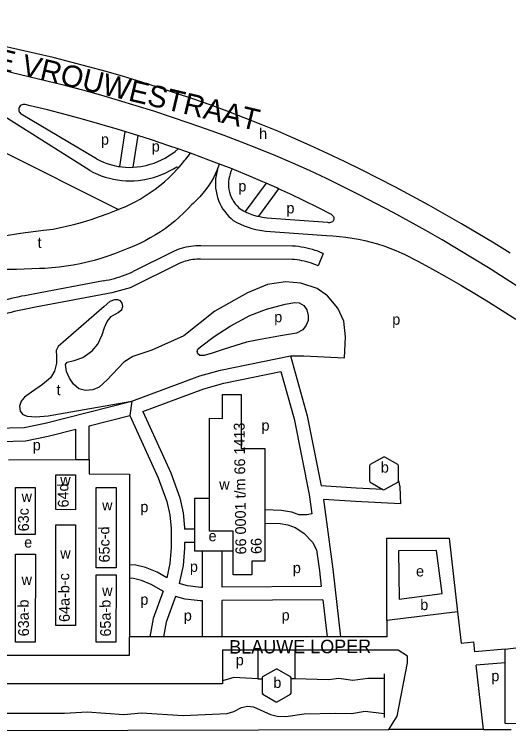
# Model space of a CAD drawing. Extents: x 161494 to 163033, y 383688 to 384862.
# Drawn here: x 162333.3 to 162517.1, y 384562.2 to 384828.7 of the extents above; entities that cross this region are included whole.
import ezdxf

# ---------------------------------------------------------------- set-up
doc = ezdxf.new("R2010")
doc.units = 0
for name, color, linetype in [('BLT_Basislijn', 7, 'Continuous'), ('BLT_Bebouwing', 7, 'Continuous'), ('BLT_Centroide', 7, 'Continuous'), ('BLT_Huisnummer', 7, 'Continuous'), ('BLT_Huisnummer_reeks', 7, 'Continuous'), ('BLT_Straatnaam', 7, 'Continuous'), ('BLT_Straatnaam_hoofdweg', 7, 'Continuous'), ('BLT_Vlakafsluiter', 7, 'Continuous')]:
    doc.layers.add(name, color=color, linetype=linetype)

msp = doc.modelspace()

# ---------------------------------------------------------------- linework, layer by layer
at = {"layer": 'BLT_Basislijn'}
for p, q in [((162361.38, 384770.68), (162323.86, 384794.28)), ((162363.88, 384775.02), (162335.93, 384791.64)), ((162309.6, 384787.43), (162372.08, 384756.07)), ((162374.39, 384785.15), (162372.4, 384772.1)), ((162379.22, 384783.64), (162377.42, 384771.83)), ((162397.07, 384774.81), (162398.79, 384777.02)), ((162403.4, 384775.36), (162398.79, 384777.02)), ((162393.74, 384772.05), (162394.6, 384771.89)), ((162408.89, 384771.07), (162409.65, 384773.01)), ((162426.93, 384765.9), (162419.17, 384755.33)), ((162431.6, 384763.82), (162424.1, 384753.58)), ((162374.26, 384756.97), (162372.08, 384756.07)), ((162427.26, 384753.06), (162449.71, 384751.4)), ((162426.8, 384748.08), (162449.34, 384746.42)), ((162436.81, 384742.53), (162402.64, 384742.61)), ((162392.77, 384740.63), (162377.48, 384733.02)), ((162436.62, 384737.54), (162402.57, 384737.61)), ((162361.15, 384675.62), (162376.28, 384679.48)), ((162361.15, 384663.08), (162361.15, 384675.62)), ((162356.15, 384663.06), (162356.15, 384674.35)), ((162331.14, 384662.94), (162356.15, 384663.06)), ((162356.15, 384663.06), (162361.15, 384663.08)), ((162361.15, 384663.08), (162361.14, 384657.72)), ((162400.33, 384637.25), (162396.65, 384637.25)), ((162400.33, 384637.25), (162400.33, 384632.25)), ((162400.33, 384632.25), (162396.65, 384632.25)), ((162403.3, 384629.13), (162410.56, 384629.14)), ((162403.3, 384615.53), (162403.3, 384629.13)), ((162410.56, 384629.14), (162414.74, 384629.14)), ((162410.56, 384615.59), (162410.56, 384629.14)), ((162376.15, 384623.95), (162376.16, 384618.93)), ((162376.16, 384618.93), (162376.17, 384597.18)), ((162447.44, 384615.89), (162410.56, 384615.59)), ((162403.3, 384597.18), (162403.3, 384610.53)), ((162448.02, 384610.89), (162410.56, 384610.59)), ((162410.56, 384597.18), (162410.56, 384610.59)), ((162448.02, 384610.89), (162449.6, 384597.18)), ((162383.67, 384597.18), (162376.17, 384597.18)), ((162403.3, 384597.18), (162388.76, 384597.18)), ((162449.6, 384597.18), (162410.56, 384597.18)), ((162504.5, 384591.5), (162504.14, 384595.33)), ((162515.79, 384592.53), (162504.5, 384591.5)), ((162515.8, 384587.51), (162515.79, 384592.53)), ((162437.61, 384592.18), (162423.88, 384592.18)), ((162423.88, 384592.18), (162423.88, 384581.56)), ((162437.61, 384592.18), (162437.61, 384581.56)), ((162515.8, 384587.51), (162505.05, 384586.53)), ((162507.72, 384562.68), (162505.05, 384586.53)), ((162470.79, 384583.35), (162470.79, 384581.63)), ((162423.88, 384581.56), (162425.45, 384581.56)), ((162437.61, 384581.56), (162436.23, 384581.56)), ((162470.79, 384581.63), (162470.79, 384568.61)), ((162470.79, 384568.61), (162470.79, 384567.08)), ((162289.61, 384562.22), (162472.53, 384562.61)), ((162507.72, 384562.68), (162472.53, 384562.61)), ((162507.72, 384562.68), (162518.08, 384562.69))]:
    msp.add_line(p, q, dxfattribs=at)
for points in [[(162431.34, 384785.21), (162425.07, 384787.77), (162418.78, 384790.26), (162412.45, 384792.67), (162406.1, 384795.01), (162399.72, 384797.27), (162393.31, 384799.45), (162386.88, 384801.56), (162380.43, 384803.6), (162373.95, 384805.55), (162367.45, 384807.44), (162360.92, 384809.24), (162354.38, 384810.97), (162347.81, 384812.62), (162341.23, 384814.19), (162334.63, 384815.68), (162328.01, 384817.1)], [(162436.9, 384773.39), (162430.54, 384776.06), (162424.15, 384778.65), (162417.74, 384781.17), (162411.29, 384783.62), (162404.82, 384785.99), (162398.32, 384788.29), (162391.79, 384790.51), (162385.24, 384792.66), (162378.66, 384794.72), (162372.06, 384796.72), (162365.44, 384798.63), (162358.79, 384800.47), (162352.13, 384802.23), (162345.44, 384803.92), (162338.74, 384805.52), (162332.01, 384807.05)], [(162337.37, 384795.18), (162336.98, 384795.23), (162336.59, 384795.2), (162336.21, 384795.1), (162335.86, 384794.92), (162335.56, 384794.67), (162335.31, 384794.36), (162335.13, 384794.02), (162335.02, 384793.64), (162334.99, 384793.25), (162335.04, 384792.86), (162335.17, 384792.49), (162335.37, 384792.15), (162335.63, 384791.86), (162335.93, 384791.64)], [(162374.39, 384785.15), (162371.59, 384786.01), (162365.16, 384787.91), (162358.7, 384789.74), (162352.22, 384791.48), (162345.73, 384793.15), (162339.21, 384794.75), (162337.37, 384795.18)], [(162379.22, 384783.64), (162378.01, 384784.03), (162374.39, 384785.15)], [(162517.69, 384739.84), (162511.71, 384743.56), (162505.69, 384747.22), (162499.63, 384750.8), (162493.53, 384754.32), (162487.39, 384757.76), (162481.21, 384761.14), (162474.99, 384764.45), (162468.73, 384767.68), (162462.44, 384770.84), (162456.12, 384773.94), (162449.75, 384776.96), (162443.36, 384779.91), (162436.93, 384782.78), (162431.34, 384785.21)], [(162394.22, 384778.64), (162390.76, 384779.84), (162384.39, 384781.98), (162379.22, 384783.64)], [(162380.94, 384772.23), (162382.41, 384772.55), (162383.86, 384772.94), (162385.29, 384773.41), (162386.69, 384773.96), (162388.06, 384774.58), (162389.39, 384775.27), (162390.69, 384776.03), (162391.94, 384776.86), (162393.15, 384777.75), (162394.22, 384778.64)], [(162398.79, 384777.02), (162397.09, 384777.64), (162394.22, 384778.64)], [(162363.88, 384775.02), (162365.14, 384774.36), (162366.44, 384773.77), (162367.77, 384773.26), (162369.12, 384772.82), (162370.5, 384772.46), (162371.9, 384772.17), (162372.4, 384772.1)], [(162394.6, 384771.89), (162395.35, 384772.72), (162396.76, 384774.42), (162397.07, 384774.81)], [(162409.65, 384773.01), (162404.68, 384774.89), (162403.4, 384775.36)], [(162372.4, 384772.1), (162373.31, 384771.97), (162374.73, 384771.84), (162376.15, 384771.8), (162377.42, 384771.83)], [(162374.26, 384756.97), (162376.26, 384757.92), (162378.22, 384758.93), (162380.15, 384760.02), (162382.03, 384761.18), (162383.87, 384762.4), (162385.66, 384763.69), (162387.41, 384765.05), (162389.11, 384766.47), (162390.75, 384767.94), (162392.34, 384769.48), (162393.87, 384771.07), (162394.6, 384771.89)], [(162377.42, 384771.83), (162377.58, 384771.83), (162379, 384771.95), (162380.41, 384772.14), (162380.94, 384772.23)], [(162381.87, 384767.32), (162383.46, 384767.66), (162385.04, 384768.08), (162386.59, 384768.57), (162388.12, 384769.14), (162389.61, 384769.78), (162391.08, 384770.5), (162392.5, 384771.29), (162393.74, 384772.05)], [(162408.89, 384771.07), (162408.15, 384769.49), (162407.34, 384767.95), (162406.46, 384766.44), (162405.51, 384764.98), (162404.5, 384763.56), (162403.42, 384762.19), (162402.28, 384760.87), (162401.08, 384759.6), (162399.82, 384758.39), (162399.31, 384757.93)], [(162408.89, 384771.07), (162408.57, 384769.93), (162408.33, 384768.77), (162408.17, 384767.6), (162408.09, 384766.42), (162408.09, 384765.23), (162408.16, 384764.05), (162408.32, 384762.88), (162408.56, 384761.72), (162408.87, 384760.58), (162409.26, 384759.46), (162409.73, 384758.37), (162410.26, 384757.31), (162410.87, 384756.3), (162411.55, 384755.32), (162412.29, 384754.4), (162413.08, 384753.52), (162413.94, 384752.71), (162414.74, 384752.03)], [(162414.3, 384771.19), (162409.97, 384772.89), (162409.65, 384773.01)], [(162414.3, 384771.19), (162413.88, 384770.3), (162413.54, 384769.38), (162413.27, 384768.44), (162413.08, 384767.47), (162412.97, 384766.49), (162412.94, 384765.51), (162412.99, 384764.53), (162413.12, 384763.55), (162413.33, 384762.59), (162413.62, 384761.65), (162413.98, 384760.74), (162414.41, 384759.85), (162414.92, 384759.01), (162415.49, 384758.21), (162416.12, 384757.46), (162416.81, 384756.76), (162417.32, 384756.32)], [(162426.93, 384765.9), (162425.69, 384766.45), (162420.48, 384768.67), (162415.24, 384770.82), (162414.3, 384771.19)], [(162561.45, 384697.94), (162555.95, 384702.2), (162550.4, 384706.41), (162544.8, 384710.54), (162539.16, 384714.61), (162533.47, 384718.62), (162527.73, 384722.56), (162521.95, 384726.44), (162516.12, 384730.25), (162510.25, 384733.99), (162504.34, 384737.66), (162498.38, 384741.27), (162492.39, 384744.8), (162486.35, 384748.27), (162480.28, 384751.67), (162474.16, 384755), (162468.01, 384758.25), (162461.82, 384761.44), (162455.6, 384764.56), (162449.34, 384767.6), (162443.04, 384770.57), (162436.9, 384773.39)], [(162361.38, 384770.68), (162362.82, 384769.93), (162364.24, 384769.27), (162365.68, 384768.69), (162367.16, 384768.19), (162368.66, 384767.76), (162370.18, 384767.41), (162371.71, 384767.14), (162373.26, 384766.94), (162374.82, 384766.83), (162376.38, 384766.8), (162377.93, 384766.84), (162379.49, 384766.97), (162381.03, 384767.17), (162381.87, 384767.32)], [(162431.6, 384763.82), (162430.87, 384764.15), (162426.93, 384765.9)], [(162451.24, 384754.25), (162446.2, 384756.84), (162441.12, 384759.35), (162436.01, 384761.79), (162431.6, 384763.82)], [(162399.31, 384757.93), (162397.81, 384756.31), (162396.25, 384754.75), (162394.63, 384753.24), (162392.96, 384751.8), (162391.24, 384750.41), (162389.48, 384749.09), (162387.66, 384747.84), (162385.8, 384746.65), (162383.9, 384745.53), (162381.96, 384744.47), (162379.98, 384743.49), (162377.97, 384742.59), (162375.93, 384741.75), (162375.52, 384741.6)], [(162372.08, 384756.07), (162371.18, 384755.69), (162368.06, 384754.49), (162364.91, 384753.36), (162361.74, 384752.3), (162358.55, 384751.32), (162355.33, 384750.42), (162352.79, 384749.77)], [(162417.32, 384756.32), (162418.52, 384755.65), (162419.17, 384755.33)], [(162419.17, 384755.33), (162419.75, 384755.05), (162421.01, 384754.52), (162422.3, 384754.06), (162423.62, 384753.69), (162424.1, 384753.58)], [(162424.1, 384753.58), (162424.96, 384753.39), (162426.31, 384753.17), (162427.26, 384753.06)], [(162451.24, 384754.25), (162451.54, 384754.06), (162451.8, 384753.81), (162451.99, 384753.5), (162452.11, 384753.16), (162452.15, 384752.81), (162452.11, 384752.45), (162451.99, 384752.11), (162451.81, 384751.8), (162451.56, 384751.55), (162451.26, 384751.35), (162450.92, 384751.23), (162450.56, 384751.18), (162450.2, 384751.21), (162449.86, 384751.33), (162449.71, 384751.4)], [(162352.79, 384749.77), (162347.84, 384748.65), (162344.2, 384748.3), (162335.61, 384747.17), (162323.38, 384745.26), (162316.09, 384744.22), (162307.76, 384743.01), (162302.29, 384742.05)], [(162414.74, 384752.03), (162416.06, 384751.29), (162417.41, 384750.62), (162418.79, 384750.02), (162420.21, 384749.49), (162421.65, 384749.04), (162423.11, 384748.67), (162424.59, 384748.37), (162426.08, 384748.16), (162426.8, 384748.08)], [(162449.34, 384746.42), (162451.76, 384746.3), (162454.17, 384746.11), (162456.57, 384745.84), (162458.96, 384745.49), (162461.34, 384745.06), (162463.7, 384744.55), (162466.04, 384743.96), (162468.37, 384743.3), (162470.67, 384742.56), (162472.94, 384741.74), (162475.19, 384740.85), (162477.41, 384739.89), (162478.22, 384739.51)], [(162375.52, 384741.6), (162373.08, 384740.56), (162370.6, 384739.6), (162368.09, 384738.71), (162365.56, 384737.9), (162363.01, 384737.16), (162360.43, 384736.51), (162357.84, 384735.93), (162355.23, 384735.42), (162352.61, 384735), (162349.97, 384734.66), (162347.33, 384734.39), (162344.67, 384734.21), (162342.71, 384734.12)], [(162402.64, 384742.61), (162401.72, 384742.61), (162400.8, 384742.58), (162399.88, 384742.51), (162398.96, 384742.4), (162398.05, 384742.25), (162397.14, 384742.07), (162396.24, 384741.85), (162395.35, 384741.6), (162394.47, 384741.31), (162393.61, 384740.98), (162392.77, 384740.63)], [(162448.18, 384739.78), (162447.19, 384740.18), (162446.19, 384740.56), (162445.18, 384740.9), (162444.16, 384741.21), (162443.13, 384741.5), (162442.09, 384741.75), (162441.04, 384741.97), (162439.99, 384742.16), (162438.93, 384742.32), (162437.87, 384742.44), (162436.81, 384742.53)], [(162448.18, 384739.78), (162446.32, 384735.14), (162445.48, 384735.49), (162444.63, 384735.81), (162443.77, 384736.11), (162442.9, 384736.38), (162442.02, 384736.63), (162441.13, 384736.85), (162440.23, 384737.04), (162439.34, 384737.21), (162438.43, 384737.34), (162437.53, 384737.46), (162436.62, 384737.54)], [(162478.22, 384739.51), (162483.55, 384736.73), (162488.84, 384733.87), (162494.09, 384730.95), (162499.31, 384727.96), (162504.48, 384724.9), (162509.61, 384721.77), (162514.7, 384718.57), (162519.75, 384715.3)], [(162402.57, 384737.61), (162401.86, 384737.61), (162401.15, 384737.59), (162400.43, 384737.54), (162399.72, 384737.46), (162399, 384737.35), (162398.3, 384737.21), (162397.6, 384737.04), (162396.91, 384736.85), (162396.22, 384736.63), (162395.55, 384736.38), (162394.89, 384736.1)], [(162342.71, 384734.12), (162334.11, 384733.78), (162330.82, 384733.78), (162323, 384732.39), (162280.47, 384726.65), (162257.2, 384725.26), (162246.61, 384724.39)], [(162394.89, 384736.1), (162376.44, 384726.92), (162369.55, 384725.1)], [(162366.48, 384729.62), (162367.52, 384729.8), (162368.55, 384730), (162369.57, 384730.22), (162370.59, 384730.48), (162371.6, 384730.76), (162372.61, 384731.07), (162373.6, 384731.41), (162374.59, 384731.78), (162375.56, 384732.17), (162376.53, 384732.58), (162377.48, 384733.02)], [(162436.03, 384701.64), (162436.03, 384701.64), (162440.92, 384701.64), (162456.13, 384700.97), (162456.47, 384708.75), (162455.82, 384714.56), (162455.82, 384714.56), (162453.66, 384719.45), (162449.76, 384724.04), (162445.86, 384726.68), (162439.9, 384728.74), (162434.16, 384729.2), (162427.41, 384728.23), (162420.08, 384725.13), (162407.94, 384718.26), (162396.3, 384709.1), (162384.41, 384703.79), (162377.35, 384701.42), (162374.01, 384699.29), (162367.88, 384692.73), (162364.94, 384690.07), (162362.49, 384689.06), (162359.86, 384688.79), (162357.3, 384689.46), (162355.29, 384691.17), (162353.8, 384693.36), (162352.75, 384695.79), (162352.35, 384698.4), (162352.98, 384699.38), (162355.64, 384699.88), (162358.79, 384701), (162362.28, 384703.56), (162362.28, 384703.56), (162364.37, 384706.07), (162364.37, 384706.07), (162365.99, 384709.48), (162366.81, 384712.25), (162367.83, 384714.43), (162369.39, 384716.25), (162371.98, 384717.8), (162373.26, 384718.9), (162373.68, 384719.99), (162373.4, 384721.3), (162372.8, 384722.17), (162371.8, 384722.52), (162370.53, 384722.54), (162368.87, 384721.91), (162368.87, 384721.91), (162366.78, 384720.01), (162349.6, 384705.21), (162348.92, 384703.61), (162349.05, 384701.59), (162348.96, 384698.91), (162348.96, 384698.91), (162348.25, 384696.03), (162346.81, 384693.43), (162346.81, 384693.43), (162343.85, 384691.05), (162339.75, 384688.19), (162337.07, 384686.32), (162337.07, 384686.32), (162335.83, 384684.84), (162335.29, 384682.99), (162335.48, 384681.07), (162336.54, 384679.81), (162338.08, 384679.25), (162341.28, 384679.03), (162345.9, 384679.35), (162345.9, 384679.35), (162354.37, 384680.84), (162377.04, 384684.84)], [(162366.48, 384729.62), (162340.31, 384724.67), (162337.25, 384724.06)], [(162337.25, 384724.06), (162335.97, 384723.82), (162334.69, 384723.55), (162333.41, 384723.27), (162332.14, 384722.98), (162330.87, 384722.66), (162329.61, 384722.33), (162328.35, 384721.98), (162327.1, 384721.61), (162325.85, 384721.23), (162324.6, 384720.83), (162323.37, 384720.41)], [(162369.55, 384725.1), (162341.26, 384719.76), (162338.19, 384719.15)], [(162338.19, 384719.15), (162336.97, 384718.92), (162335.76, 384718.67), (162334.54, 384718.4), (162333.34, 384718.12), (162332.13, 384717.82), (162330.93, 384717.51), (162329.73, 384717.17), (162328.54, 384716.83), (162327.35, 384716.46), (162326.17, 384716.08), (162325, 384715.68)], [(162377.04, 384684.84), (162402.29, 384694.22), (162410.04, 384696.4), (162436.03, 384701.64)], [(162436.03, 384701.64), (162442.19, 384679.4), (162447.39, 384653.31)], [(162381.08, 384681.01), (162403.84, 384689.46), (162411.22, 384691.54), (162432.46, 384695.82), (162437.33, 384678.25), (162442.92, 384650.12), (162443.9, 384642.93)], [(162220.67, 384686.8), (162219.95, 384686.26), (162220.83, 384685.67), (162229.27, 384685.67), (162241.18, 384684.93), (162250.36, 384682.68), (162266.46, 384675.07), (162272.51, 384674.26), (162290.25, 384672.71), (162297.71, 384672.56), (162307.17, 384673.99), (162314.91, 384674.48), (162336.96, 384675.07), (162344.86, 384676.63), (162377.04, 384684.84)], [(162381.08, 384681.01), (162391.51, 384658.11), (162394.82, 384648.81), (162396.05, 384643.27), (162396.65, 384637.66), (162396.65, 384637.25)], [(162376.28, 384679.48), (162386.87, 384656.23), (162390.01, 384647.43), (162391.1, 384642.47), (162391.65, 384637.39), (162391.65, 384630.31), (162391.12, 384624.45), (162389.99, 384619.09)], [(162318.76, 384669.58), (162337.51, 384670.08), (162345.96, 384671.75), (162356.15, 384674.35)], [(162361.14, 384657.72), (162376.14, 384657.7), (162376.15, 384623.95)], [(162476.16, 384655.11), (162476.67, 384652.93), (162476.94, 384646.6), (162460.11, 384647.45), (162448.22, 384648.24)], [(162470.39, 384651.94), (162460.41, 384652.44), (162447.39, 384653.31)], [(162405.91, 384648.64), (162400.33, 384648.64), (162400.33, 384637.25)], [(162448.22, 384648.24), (162451.74, 384622.25), (162454.64, 384597.18)], [(162426.44, 384644.45), (162432.62, 384644.27), (162436.35, 384643.62), (162439.33, 384642.54)], [(162443.9, 384642.93), (162442.24, 384642.54), (162439.33, 384642.54)], [(162426.44, 384639.45), (162432.12, 384639.29), (162435.05, 384638.78), (162437.76, 384637.78), (162441.01, 384635.69), (162444.24, 384632.34), (162445.72, 384629.44)], [(162396.65, 384632.25), (162396.65, 384630.08), (162396.07, 384623.71), (162394.65, 384616.96)], [(162400.33, 384632.25), (162400.33, 384629.13), (162403.3, 384629.13)], [(162445.72, 384629.44), (162446.78, 384621.63), (162447.44, 384615.89)], [(162389.99, 384619.09), (162386.43, 384621.15), (162382.1, 384622.92), (162378.45, 384623.76), (162376.15, 384623.95)], [(162388.66, 384614.16), (162387.89, 384614.52), (162384.22, 384616.65), (162380.58, 384618.14), (162377.68, 384618.81), (162376.16, 384618.93)], [(162403.3, 384615.53), (162402.66, 384615.53), (162397.76, 384616.09), (162394.65, 384616.96)], [(162388.66, 384614.16), (162384.98, 384603.97), (162383.67, 384597.18)], [(162393.25, 384612.16), (162389.81, 384602.64), (162388.76, 384597.18)], [(162403.3, 384610.53), (162402.4, 384610.53), (162396.79, 384611.16), (162393.25, 384612.16)], [(162498.14, 384606.44), (162499.5, 384594.76), (162504.14, 384595.33)], [(162471.86, 384603.19), (162471.85, 384597.18), (162454.64, 384597.18)], [(162515.79, 384592.53), (162581.83, 384600.89), (162581.84, 384603.86), (162583.3, 384603.87)], [(162298.77, 384602.26), (162298.77, 384590.27), (162376.17, 384590.27), (162376.17, 384597.18)], [(162410.73, 384580.75), (162410.73, 384579.6), (162269.46, 384579.6), (162269.33, 384590.95), (162207.44, 384590.95)], [(162423.88, 384592.18), (162410.73, 384592.18), (162410.73, 384580.75)], [(162472.53, 384562.61), (162475.61, 384567.6), (162479.45, 384587.5), (162479.45, 384589.91), (162476.02, 384592.18), (162437.61, 384592.18)], [(162520.96, 384564.8), (162515.82, 384564.86), (162515.8, 384587.51)], [(162423.88, 384581.56), (162414.96, 384581.99), (162410.73, 384580.75)], [(162470.79, 384581.63), (162464.77, 384581.63), (162459.17, 384580.92), (162454, 384581.67), (162450.1, 384581.09), (162437.61, 384581.56)], [(162327.46, 384568.68), (162352.01, 384568.73), (162360.38, 384569.21), (162374.08, 384568.21), (162380.6, 384568.87), (162396.16, 384567.82), (162412.46, 384568.66), (162414.96, 384569.38), (162417.76, 384570.87), (162420, 384571.38), (162422.28, 384571.12), (162428.56, 384568.26), (162431.04, 384567.59), (162434.23, 384567.54), (162441.14, 384568.44), (162452.87, 384568.71), (162458.68, 384568.55), (162463.78, 384569.52), (162470.79, 384568.61)]]:
    msp.add_lwpolyline(points, dxfattribs=at)
msp.add_lwpolyline([(162407.68, 384708.81), (162413.57, 384712.69), (162420.94, 384716.65), (162427.11, 384719.01), (162434.06, 384720.95), (162437.62, 384721.55), (162439.23, 384721.35), (162440.91, 384720.38), (162442.03, 384718.8), (162442.53, 384716.72), (162442.53, 384714.82), (162441.89, 384713.03), (162440.55, 384711.29), (162438.27, 384710.15), (162432.3, 384709.08), (162424.08, 384707.61), (162419.61, 384706.81), (162411.38, 384704.12), (162406.88, 384702.65), (162403.87, 384701.85), (162402.36, 384701.76), (162401.54, 384702.45), (162401.26, 384703.24), (162401.52, 384704.18), (162402.52, 384705.04)], close=True, dxfattribs=at)
at = {"layer": 'BLT_Bebouwing'}
for p, q in [((162426.44, 384644.45), (162426.44, 384639.45)), ((162498.14, 384606.44), (162471.86, 384603.19)), ((162341.13, 384595.12), (162333.77, 384595.12)), ((162371.11, 384595.15), (162363.76, 384595.14))]:
    msp.add_line(p, q, dxfattribs=at)
for points in [[(162405.91, 384648.64), (162405.9, 384678.44), (162410.68, 384678.41), (162410.71, 384687.23), (162417.61, 384687.25), (162417.61, 384667.26), (162426.43, 384667.26), (162426.44, 384644.45)], [(162470.54, 384664.03), (162465.63, 384661.2), (162465.39, 384660.8), (162465.38, 384655.12), (162465.62, 384654.7), (162470.39, 384651.94)], [(162476.16, 384655.11), (162476.19, 384660.79), (162475.94, 384661.21), (162471.03, 384664.03), (162470.54, 384664.03)], [(162470.98, 384651.89), (162475.94, 384654.69), (162476.16, 384655.11)], [(162470.39, 384651.94), (162470.53, 384651.85), (162470.98, 384651.89)], [(162414.74, 384629.14), (162414.74, 384636.42), (162405.91, 384636.41), (162405.91, 384648.64)], [(162426.44, 384639.45), (162426.45, 384625.25), (162421.65, 384625.27), (162421.64, 384620.21), (162414.73, 384620.18), (162414.74, 384629.14)], [(162471.86, 384603.19), (162471.88, 384633.8), (162494.97, 384633.78), (162498.14, 384606.44)], [(162333.77, 384595.12), (162333.77, 384627.94), (162341.16, 384627.92), (162341.13, 384595.12)], [(162363.76, 384595.14), (162363.75, 384620.16), (162371.16, 384620.18), (162371.11, 384595.15)], [(162436.23, 384581.56), (162436.23, 384581.86), (162435.98, 384582.28), (162431.06, 384585.12), (162430.72, 384585.11), (162425.59, 384582.19)], [(162425.59, 384582.19), (162425.45, 384581.87), (162425.45, 384581.56)], [(162425.45, 384581.56), (162425.44, 384576.17), (162425.67, 384575.74), (162430.59, 384572.92), (162431.08, 384572.91), (162435.99, 384575.76), (162436.24, 384576.18), (162436.23, 384581.56)]]:
    msp.add_lwpolyline(points, dxfattribs=at)
for points in [[(162348.76, 384657.36), (162356.14, 384657.39), (162356.1, 384644.43), (162348.76, 384644.45)], [(162333.74, 384652.72), (162341.14, 384652.72), (162341.13, 384635.17), (162333.77, 384635.15)], [(162363.76, 384652.72), (162371.14, 384652.71), (162371.15, 384622.75), (162363.76, 384622.75)], [(162348.76, 384638.79), (162356.12, 384638.82), (162356.12, 384601.33), (162348.74, 384601.36)], [(162476.19, 384629.09), (162476.44, 384611.11), (162492.36, 384613.2), (162490.32, 384629.21)]]:
    msp.add_lwpolyline(points, close=True, dxfattribs=at)
at = {"layer": 'BLT_Vlakafsluiter'}
for p, q in [((162377.04, 384684.84), (162376.28, 384679.48)), ((162388.76, 384597.18), (162383.67, 384597.18)), ((162410.56, 384597.18), (162403.3, 384597.18)), ((162454.64, 384597.18), (162449.6, 384597.18))]:
    msp.add_line(p, q, dxfattribs=at)

# ---------------------------------------------------------------- texts
at = {"layer": 'BLT_Centroide'}
for s, p in [('h', (162424.35, 384782.41)), ('p', (162365.54, 384780.23)), ('p', (162384.44, 384777.68)), ('p', (162416.63, 384762.85)), ('p', (162434.51, 384754.67)), ('t', (162341.99, 384741.82)), ('p', (162429.96, 384714.17)), ('p', (162473.83, 384713.25)), ('t', (162349.05, 384687.04)), ('p', (162425.23, 384673.82)), ('p', (162340.2, 384666.53)), ('b', (162469.59, 384658.23)), ('w', (162350.41, 384653.57)), ('w', (162409.51, 384651.86)), ('w', (162336.03, 384647.32)), ('w', (162365.98, 384644.14)), ('p', (162380.19, 384643.52)), ('e', (162405.54, 384632.69)), ('e', (162337.01, 384630.33)), ('w', (162350.41, 384626.21)), ('p', (162398.6, 384621.3)), ('p', (162436.88, 384620.82)), ('e', (162482.67, 384619.6)), ('w', (162336.03, 384616.42)), ('w', (162365.98, 384612.3)), ('p', (162380.19, 384609.06)), ('b', (162484.24, 384607.08)), ('p', (162396.35, 384603.11)), ('p', (162432.7, 384603.23)), ('p', (162415.67, 384586.53)), ('b', (162429.62, 384578.12)), ('p', (162510.67, 384580.64))]:
    msp.add_text(s, height=4, dxfattribs=at).set_placement(p)
at = {"layer": 'BLT_Huisnummer'}
for s, p in [('64d', (162353.54, 384645.28)), ('63c', (162338.78, 384636.41))]:
    msp.add_text(s, height=4, rotation=90.77, dxfattribs=at).set_placement(p)
at = {"layer": 'BLT_Huisnummer_reeks'}
for s, p in [('66 0001 t/m 66 1413', (162419.58, 384627.81)), ('65c-d', (162368.82, 384624.82)), ('66', (162425.32, 384627.98)), ('64a-b-c', (162353.98, 384602.69)), ('63a-b', (162338.81, 384597.35)), ('65a-b', (162369.27, 384597.26))]:
    msp.add_text(s, height=4, rotation=90.77, dxfattribs=at).set_placement(p)
at = {"layer": 'BLT_Straatnaam'}
msp.add_text('BLAUWE LOPER', height=5, rotation=0.2472, dxfattribs=at).set_placement((162413.25, 384590.89))
at = {"layer": 'BLT_Straatnaam_hoofdweg'}
msp.add_text('ONZE LIEVE VROUWESTRAAT', height=8, rotation=346.6603, dxfattribs=at).set_placement((162271.26, 384821.4))

doc.saveas('drawing.dxf')
